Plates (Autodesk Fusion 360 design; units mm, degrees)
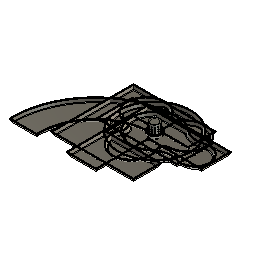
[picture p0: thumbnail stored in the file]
parameter "wall" = 1.35 comment "Wall Thikckness (Advance setting)"
parameter "height" = 75 (= "Size * 0.75") comment "Vase Hight (Advance setting)"
parameter "tolerance" = 0.5 comment "Clerance needed between parts (Advance setting)"
parameter "Size" = 100 comment "Vase top Diameter (Basic setting)Use 70 or more."
parameter "d14" = -11 (= "-Size * 0.11") comment "Middle Section, offset from Top Diameter (Advance setting)"
parameter "d15" = 22.5 comment "Angle Middle Section (Advance setting)"
parameter "d16" = -17 (= "-Size * 0.17") comment "Bottom Section, offset from Top Diameter (Advance setting)"
parameter "d17" = 0.1 comment "Angle Bottom Section (Advance setting)"
parameter "d18" = 45 comment "Angle Top Section (Advance setting)"
parameter "d81" = 76 (= "Size * 0.76") comment "Water Colum Distance from vase center (Advamce setting)"
sketch "Sketch11" plane through (0, 0, 0) normal (1, 0, 0) x axis (0, 1, 0)
  line L1 (102.8937, 10) -> (104.2937, 10)
  line L2 (0, 2) -> (97.5108, 2)
  line L3 (99.8202, 0) -> (0, 0)
  line L4 (99.2428, 3) -> (102.3257, 8.3397)
  line L5 (102.5937, 9.3397) -> (102.5937, 9.7)
  line L6 (104.5937, 9.7) -> (104.5937, 9.0718)
  line L7 (104.1917, 7.5718) -> (99.8202, 0)
  line L8 (0, 2) -> (0, 0)
  line L9 (97.5108, 0) -> (97.5108, 2)
  line L10 (104.5937, 9.7) -> (104.5937, 9.0718)
  line L11 (99.2428, 3) -> (102.3257, 8.3397)
  line L12 (97.5108, 0) -> (97.5108, 2)
  line L13 (102.8937, 10) -> (104.2937, 10)
  line L14 (102.5937, 9.3397) -> (102.5937, 9.7)
  line L15 (104.1917, 7.5718) -> (99.8202, 0)
  line L16 (97.5937, 9.3397) -> (97.5937, 9.7)
  line L17 (99.1917, 7.5718) -> (94.8202, 0)
  line L18 (94.2428, 3) -> (97.3257, 8.3397)
  line L19 (99.5937, 9.7) -> (99.5937, 9.0718)
  line L20 (97.8937, 10) -> (99.2937, 10)
  line L21 (97.8937, 10) -> (99.2937, 10)
  line L22 (94.2428, 3) -> (97.3257, 8.3397)
  line L23 (92.5108, 0) -> (92.5108, 2)
  line L24 (99.5937, 9.7) -> (99.5937, 9.0718)
  line L25 (97.5937, 9.3397) -> (97.5937, 9.7)
  line L26 (99.1917, 7.5718) -> (94.8202, 0)
  line L27 (92.5108, 0) -> (92.5108, 2)
  line L28 (92.5937, 9.3397) -> (92.5937, 9.7)
  line L29 (94.1917, 7.5718) -> (89.8202, 0)
  line L30 (89.2428, 3) -> (92.3257, 8.3397)
  line L31 (94.5937, 9.7) -> (94.5937, 9.0718)
  line L32 (92.8937, 10) -> (94.2937, 10)
  line L33 (92.8937, 10) -> (94.2937, 10)
  line L34 (89.2428, 3) -> (92.3257, 8.3397)
  line L35 (87.5108, 0) -> (87.5108, 2)
  line L36 (94.5937, 9.7) -> (94.5937, 9.0718)
  line L37 (92.5937, 9.3397) -> (92.5937, 9.7)
  line L38 (94.1917, 7.5718) -> (89.8202, 0)
  line L39 (87.5108, 0) -> (87.5108, 2)
  line L40 (87.5937, 9.3397) -> (87.5937, 9.7)
  line L41 (89.1917, 7.5718) -> (84.8202, 0)
  line L42 (84.2428, 3) -> (87.3257, 8.3397)
  line L43 (89.5937, 9.7) -> (89.5937, 9.0718)
  line L44 (87.8937, 10) -> (89.2937, 10)
  line L45 (87.8937, 10) -> (89.2937, 10)
  line L46 (84.2428, 3) -> (87.3257, 8.3397)
  line L47 (82.5108, 0) -> (82.5108, 2)
  line L48 (89.5937, 9.7) -> (89.5937, 9.0718)
  line L49 (87.5937, 9.3397) -> (87.5937, 9.7)
  line L50 (89.1917, 7.5718) -> (84.8202, 0)
  line L51 (82.5108, 0) -> (82.5108, 2)
  line L52 (82.5937, 9.3397) -> (82.5937, 9.7)
  line L53 (84.1917, 7.5718) -> (79.8202, 0)
  line L54 (79.2428, 3) -> (82.3257, 8.3397)
  line L55 (84.5937, 9.7) -> (84.5937, 9.0718)
  line L56 (82.8937, 10) -> (84.2937, 10)
  line L57 (82.8937, 10) -> (84.2937, 10)
  line L58 (79.2428, 3) -> (82.3257, 8.3397)
  line L59 (77.5108, 0) -> (77.5108, 2)
  line L60 (84.5937, 9.7) -> (84.5937, 9.0718)
  line L61 (82.5937, 9.3397) -> (82.5937, 9.7)
  line L62 (84.1917, 7.5718) -> (79.8202, 0)
  line L63 (77.5108, 0) -> (77.5108, 2)
  line L64 (77.5937, 9.3397) -> (77.5937, 9.7)
  line L65 (79.1917, 7.5718) -> (74.8202, 0)
  line L66 (74.2428, 3) -> (77.3257, 8.3397)
  line L67 (79.5937, 9.7) -> (79.5937, 9.0718)
  line L68 (77.8937, 10) -> (79.2937, 10)
  line L69 (77.8937, 10) -> (79.2937, 10)
  line L70 (74.2428, 3) -> (77.3257, 8.3397)
  line L71 (72.5108, 0) -> (72.5108, 2)
  line L72 (79.5937, 9.7) -> (79.5937, 9.0718)
  line L73 (77.5937, 9.3397) -> (77.5937, 9.7)
  line L74 (79.1917, 7.5718) -> (74.8202, 0)
  line L75 (72.5108, 0) -> (72.5108, 2)
  line L76 (72.5937, 9.3397) -> (72.5937, 9.7)
  line L77 (74.1917, 7.5718) -> (69.8202, 0)
  line L78 (69.2428, 3) -> (72.3257, 8.3397)
  line L79 (74.5937, 9.7) -> (74.5937, 9.0718)
  line L80 (72.8937, 10) -> (74.2937, 10)
  line L81 (72.8937, 10) -> (74.2937, 10)
  line L82 (69.2428, 3) -> (72.3257, 8.3397)
  line L83 (67.5108, 0) -> (67.5108, 2)
  line L84 (74.5937, 9.7) -> (74.5937, 9.0718)
  line L85 (72.5937, 9.3397) -> (72.5937, 9.7)
  line L86 (74.1917, 7.5718) -> (69.8202, 0)
  line L87 (67.5108, 0) -> (67.5108, 2)
  line L88 (67.5937, 9.3397) -> (67.5937, 9.7)
  line L89 (69.1917, 7.5718) -> (64.8202, 0)
  line L90 (64.2428, 3) -> (67.3257, 8.3397)
  line L91 (69.5937, 9.7) -> (69.5937, 9.0718)
  line L92 (67.8937, 10) -> (69.2937, 10)
  line L93 (67.8937, 10) -> (69.2937, 10)
  line L94 (64.2428, 3) -> (67.3257, 8.3397)
  line L95 (62.5108, 0) -> (62.5108, 2)
  line L96 (69.5937, 9.7) -> (69.5937, 9.0718)
  line L97 (67.5937, 9.3397) -> (67.5937, 9.7)
  line L98 (69.1917, 7.5718) -> (64.8202, 0)
  line L99 (62.5108, 0) -> (62.5108, 2)
  line L100 (62.5937, 9.3397) -> (62.5937, 9.7)
  line L101 (64.1917, 7.5718) -> (59.8202, 0)
  line L102 (59.2428, 3) -> (62.3257, 8.3397)
  line L103 (64.5937, 9.7) -> (64.5937, 9.0718)
  line L104 (62.8937, 10) -> (64.2937, 10)
  line L105 (62.8937, 10) -> (64.2937, 10)
  line L106 (59.2428, 3) -> (62.3257, 8.3397)
  line L107 (57.5108, 0) -> (57.5108, 2)
  line L108 (64.5937, 9.7) -> (64.5937, 9.0718)
  line L109 (62.5937, 9.3397) -> (62.5937, 9.7)
  line L110 (64.1917, 7.5718) -> (59.8202, 0)
  line L111 (57.5108, 0) -> (57.5108, 2)
  line L112 (57.5937, 9.3397) -> (57.5937, 9.7)
  line L113 (59.1917, 7.5718) -> (54.8202, 0)
  line L114 (54.2428, 3) -> (57.3257, 8.3397)
  line L115 (59.5937, 9.7) -> (59.5937, 9.0718)
  line L116 (57.8937, 10) -> (59.2937, 10)
  line L117 (57.8937, 10) -> (59.2937, 10)
  line L118 (54.2428, 3) -> (57.3257, 8.3397)
  line L119 (52.5108, 0) -> (52.5108, 2)
  line L120 (59.5937, 9.7) -> (59.5937, 9.0718)
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  point P1 (0, 0)
  point P30 (0, 0)
  point P4 (97.5108, 2)
  point P32 (97.5108, 2)
  point P33 (97.5108, 0)
  point P36 (97.5108, 2)
  point P44 (97.5108, 2)
  coincident P1 P30
  coincident P4 P32
  coincident L3 P33
  perpendicular L3 L9
  coincident P36 P44
  dimension "d140" R-Pattern1-uDistance = -5
  dimension "d141" R-Pattern1-vDistance = 0
derived_base_feature "Derived Base Feature" bodies "Body51"
move "Move4"
sketch "Sketch12" plane through (0, 0, 0) normal (0, 0, 1) x axis (1, 0, 0)
  line L1 (-92.5, -37.5) -> (92.5, -37.5)
  line L2 (-92.5, 37.5) -> (-92.5, -37.5)
  line L3 (92.5, 37.5) -> (-92.5, 37.5)
  line L4 (92.5, -37.5) -> (92.5, 37.5)
  line L5 (-92.5, 37.5) -> (92.5, -37.5)
  line L6 (92.5, 37.5) -> (-92.5, -37.5)
  line L7 (130, 40) -> (-55, 40)
  line L8 (130, -15) -> (130, 40)
  line L9 (-55, -145) -> (0, -145)
  line L10 (-55, 40) -> (-55, -145)
  line L11 (0, -15) -> (0, -145)
  line L12 (130, -15) -> (0, -15)
  line L13 (0, -15) -> (0, 0)
  line L14 (67.5, 65) -> (-117.5, 65)
  line L15 (-117.5, -120) -> (67.5, -120)
  line L16 (-117.5, 65) -> (-117.5, -120)
  line L17 (-67.5, -70) -> (67.5, -70)
  line L18 (-67.5, 15) -> (-67.5, -70)
  line L19 (67.5, 15) -> (-67.5, 15)
  line L20 (67.5, 15) -> (67.5, 65)
  line L21 (67.5, -120) -> (67.5, -70)
  line L22 (0, 15) -> (0, 0)
  point P6 (0, 0)
  point P1 (0, 0)
  point P13 (0, 0)
  point P14 (0, -15)
  point P11 (0, -15)
  point P23 (0, 0)
  point P24 (0, 15)
  point P4 (-92.5, 37.5)
  point P5 (92.5, 37.5)
  point P3 (-92.5, -37.5)
  point P7 (-55, 40)
  point P8 (130, 40)
  point P9 (-55, -145)
  point P15 (-117.5, 65)
  point P16 (67.5, 65)
  point P18 (-117.5, -120)
  horizontal L1
  perpendicular L1 L2
  parallel L1 L3
  parallel L2 L4
  coincident L5 P6
  coincident L6 P6
  horizontal L7
  vertical L8
  horizontal L9
  vertical L10
  coincident P1 P6
  coincident P6 P13
  vertical L13
  coincident L12 P14
  coincident P11 L13
  horizontal L14
  vertical L20
  horizontal L15
  vertical L16
  collinear L20 L21
  coincident P6 P23
  perpendicular L19 L22
  midpoint L19 P24
  dimension "d145" distance P4 P5 = 185
  dimension "d146" distance P3 P4 = 75
  dimension "d155" distance P7 P8 = 185
  dimension "d156" distance P7 P9 = 185
  dimension "d157" distance ORIGIN L10 = 55
  dimension "d159" distance P13 P14 = 15
  dimension "d160" distance P15 P16 = 185
  dimension "d161" distance P15 P18 = 185
  dimension "d162" = 50
  dimension "d163" distance P23 P24 = 15
sweep "Sweep2" sketch "Sketch11" TwistAngle 0 TaperAngle 0
extrude "Extrude17" add sketch "Sketch12" profile of L1 L2 L3 L4 along normal blind 2
sweep "Sweep3" sketch "Sketch11" TwistAngle 0 TaperAngle 0
extrude "Extrude18" add sketch "Sketch12" profile of L1 L3 L4 L7 L8 L9 L10 L11 L12 L21 L15 L17 L19 along normal blind 2
sweep "Sweep4" sketch "Sketch11" TwistAngle 0 TaperAngle 0
extrude "Extrude19" add sketch "Sketch12" profile of L1 L2 L3 L7 L10 L11 L14 L21 L15 L16 L17 L19 L18 along normal blind 2
sketch "Sketch13" plane through (0, 0, 0) normal (0, 0, 1) x axis (1, 0, 0)
  curve K1 (95, 0) -> (-95, 0)
  curve K2 (0, 42.5) -> (0, -42.5)
  line L1 (100, 0) -> (0, 0)
  line L2 (0, -2) -> (0, 53)
  line L3 (-200, -147) -> (-145, -147)
  line L4 (-145, -147) -> (0, -147)
  line L5 (0, -147) -> (0, -2)
  line L6 (0, 53) -> (0, 0)
  line L7 (0, -57.735) -> (-50, 28.8675)
  line L8 (50, 28.8675) -> (0, -57.735)
  line L9 (-50, 28.8675) -> (50, 28.8675)
  line L10 (0, 28.8675) -> (0, 0)
  closed curve K3 centre (0, 0)
  arc A1 centre (72.2188, 82.9726) radius 60 clockwise from (91.2688, 26.0771) to (32.8267, 37.7148)
  arc A2 centre (72.2188, -82.9726) radius 60 clockwise from (32.8267, -37.7148) to (91.2688, -26.0771)
  arc A3 centre (100, 0) radius 27.5 clockwise from (91.2688, 26.0771) to (91.2688, -26.0771)
  arc A4 centre (0, 0) radius 50 clockwise from (32.8267, -37.7148) to (32.8267, 37.7148)
  arc A5 centre (0, -147) radius 145 clockwise from (-145, -147) to (0, -2)
  arc A6 centre (0, -147) radius 200 clockwise from (-200, -147) to (0, 53)
  circle C1 centre (0, 0) radius 81.4601
  arc A7 centre (0, 62.0338) radius 20 clockwise from (16.6667, 50.9783) to (-16.6667, 50.9783)
  arc A8 centre (50, 28.8675) radius 40 clockwise from (16.6667, 50.9783) to (52.4819, -11.0554)
  arc A9 centre (53.7228, -31.0169) radius 20 clockwise from (35.8152, -39.9229) to (52.4819, -11.0554)
  arc A10 centre (0, -57.735) radius 40 clockwise from (35.8152, -39.9229) to (-35.8152, -39.9229)
  arc A11 centre (-53.7228, -31.0169) radius 20 clockwise from (-52.4819, -11.0554) to (-35.8152, -39.9229)
  arc A12 centre (-50, 28.8675) radius 40 clockwise from (-52.4819, -11.0554) to (-16.6667, 50.9783)
  point P1 (0, 0)
  point P2 (0, 0)
  point P3 (-95, 0)
  point P4 (95, 0)
  point P5 (0, -42.5)
  point P6 (0, 42.5)
  point P7 (0, 0)
  point P9 (0, 0)
  point P8 (100, 0)
  point P10 (100, 0)
  point P20 (0, -147)
  point P23 (0, -147)
  point P24 (0, -147)
  point P25 (0, 0)
  point P17 (0, 53)
  point P26 (0, 53)
  point P31 (0, 0)
  point P32 (0, 0)
  point P33 (0, 28.8675)
  point P28 (-50, 28.8675)
  point P34 (-50, 28.8675)
  point P30 (50, 28.8675)
  point P35 (50, 28.8675)
  point P29 (0, -57.735)
  point P36 (0, -57.735)
  coincident P1 P2
  horizontal K1
  coincident K3 P3
  coincident K3 P4
  coincident K3 P5
  coincident K3 P6
  coincident P7 P9
  horizontal L1
  coincident P8 P10
  equal A1 A2
  tangent A1 A4
  tangent A1 A3
  tangent A2 A3
  tangent A2 A4
  coincident P2 P7
  vertical L2
  concentric A5 A6
  coincident P20 P23
  parallel L3 L4
  coincident P20 P24
  parallel L2 L5
  coincident P7 P25
  parallel K2 L6
  coincident P17 P26
  concentric K3 C1
  coincident P31 P32
  midpoint L9 P33
  coincident P28 P34
  coincident P30 P35
  coincident P29 P36
  equal A8 A12
  equal A10 A12
  equal A7 A11
  equal A7 A9
  tangent A7 A8
  tangent A8 A9
  tangent A9 A10
  tangent A10 A11
  tangent A11 A12
  tangent A7 A12
  vertical L10
  coincident P1 P31
  dimension "d180" distance K3 = 190
  dimension "d181" = 85
  dimension "d182" diameter A4 = 100
  dimension "d183" diameter A3 = 55
  dimension "d185" radius A1 = 60
  dimension "d186" distance P9 P10 = 100
  dimension "d191" radius A5 = 145
  dimension "d192" radius A6 = 200
  dimension "d193" angle L2 L3 = 90
  dimension "d194" distance P25 P26 = 53
  dimension "d197" diameter A8 = 80
  dimension "d198" diameter A7 = 40
  dimension "d200" distance P29 P30 = 100
sweep "Sweep5" sketch "Sketch11" TwistAngle 0 TaperAngle 0
extrude "Extrude20" add sketch "Sketch13" profile of K3 A4 A1 A2 L2 A6 A5 L6 C1 A12 A8 A10 A7 A9 A11 along normal blind 2
sweep "Sweep6" sketch "Sketch11" TwistAngle 0 TaperAngle 0
extrude "Extrude21" add sketch "Sketch13" profile of K3 A4 A3 A1 A2 L2 A5 L6 C1 A8 A7 A9 A11 along normal blind 2
sweep "Sweep7" sketch "Sketch11" TwistAngle 0 TaperAngle 0
extrude "Extrude22" add sketch "Sketch13" profile of K3 A4 A1 A2 L2 A6 A5 L6 C1 A12 A8 A10 A7 A9 A11 along normal blind 2
sweep "Sweep8" sketch "Sketch11" TwistAngle 0 TaperAngle 0
extrude "Extrude23" add sketch "Sketch13" profile of K3 A4 L2 L3 A6 A5 L6 C1 A12 A7 A11 along normal blind 2
named bodies: "Body51"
